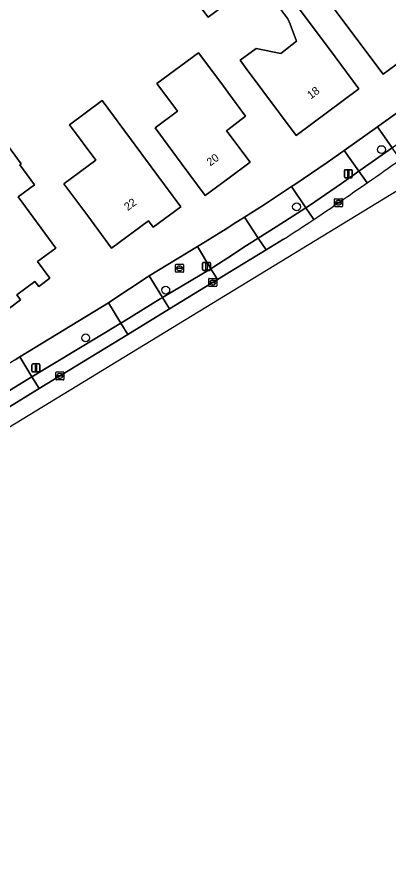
# Model space of a CAD drawing. Extents: x 156702 to 158052, y 387630 to 388992.
# Drawn here: x 157473.7 to 157520.1, y 387761.3 to 387868.3 of the extents above; entities that cross this region are included whole.
import ezdxf

# ---------------------------------------------------------------- set-up
doc = ezdxf.new("R2010")
doc.units = 0
for name, color, linetype in [('IMGEO_Boom', 7, 'Continuous'), ('IMGEO_Brandkraan', 7, 'Continuous'), ('IMGEO_Erf', 7, 'Continuous'), ('IMGEO_Kolk', 7, 'Continuous'), ('IMGEO_Lichtmast', 7, 'Continuous'), ('IMGEO_Pand', 7, 'Continuous'), ('IMGEO_Pand_nummerreeks', 7, 'Continuous'), ('IMGEO_Parkeervlak_open', 7, 'Continuous'), ('IMGEO_Rijbaan_lokaal_open', 7, 'Continuous'), ('IMGEO_Voetpad_open', 7, 'Continuous')]:
    doc.layers.add(name, color=color, linetype=linetype)

msp = doc.modelspace()

# ---------------------------------------------------------------- linework, layer by layer
at = {"layer": 'IMGEO_Boom'}
for centre in [(157519.17, 387851.76), (157508.58, 387844.62), (157492.26, 387834.21), (157482.27, 387828.25)]:
    msp.add_circle(centre, 0.489, dxfattribs=at)
at = {"layer": 'IMGEO_Brandkraan'}
for p, q in [((157493.48, 387836.52), (157493.48, 387837.37)), ((157493.56, 387837.44), (157494.41, 387837.44)), ((157493.74, 387836.94), (157493.74, 387836.95)), ((157494.18, 387836.9), (157493.78, 387836.9)), ((157493.79, 387836.99), (157494.18, 387836.99)), ((157493.97, 387837.22), (157494, 387837.22)), ((157493.99, 387836.66), (157493.97, 387836.66)), ((157494.23, 387836.95), (157494.23, 387836.94)), ((157494.48, 387837.37), (157494.48, 387836.52)), ((157494.41, 387836.44), (157493.56, 387836.44))]:
    msp.add_line(p, q, dxfattribs=at)
for points in [[(157493.48, 387836.52), (157493.48, 387837.37)], [(157493.56, 387837.44), (157494.41, 387837.44)], [(157494.48, 387837.37), (157494.48, 387836.52)], [(157494.41, 387836.44), (157493.56, 387836.44)]]:
    msp.add_lwpolyline(points, dxfattribs=at)
for centre, radius, start, end in [((157493.56, 387837.37), 0.0765, 91.552, 178.448), ((157493.56, 387837.37), 0.0765, 91.552, 178.448), ((157493.56, 387836.52), 0.0765, 181.552, 268.448), ((157493.56, 387836.52), 0.0765, 181.552, 268.448), ((157493.78, 387836.95), 0.0403, 85.8775, 175.7526), ((157493.78, 387836.94), 0.0366, 178.938, 274.7102), ((157494.19, 387836.95), 0.0386, 1.7309, 96.639), ((157494.18, 387836.94), 0.043, 264.8664, 352.4533), ((157494.41, 387837.37), 0.0765, 1.552, 88.448), ((157494.41, 387837.37), 0.0765, 1.552, 88.448), ((157494.41, 387836.52), 0.0765, 271.552, 358.448), ((157494.41, 387836.52), 0.0765, 271.552, 358.448)]:
    msp.add_arc(centre, radius, start, end, dxfattribs=at)
for centre, major_axis, ratio, start_param, end_param in [((157493.97, 387836.94), (-0.387, 0.002), 0.722429, 4.712389, 7.853982), ((157493.99, 387836.94), (-0.39, 0.002), 0.717154, 1.570796, 4.712389)]:
    msp.add_ellipse(centre, major_axis=major_axis, ratio=ratio, start_param=start_param, end_param=end_param, dxfattribs=at)
at = {"layer": 'IMGEO_Erf'}
for points in [[(157500, 387879.97), (157500.65, 387880.45), (157513.38, 387863.36), (157516.36, 387859.35), (157508.54, 387853.53), (157502.31, 387861.9), (157501.54, 387862.92), (157503.54, 387864.37), (157506.6, 387863.76), (157508.57, 387865.29), (157507.77, 387867.43), (157507.48, 387868.08), (157506.51, 387869.44), (157505.67, 387870.37), (157504.42, 387871.38), (157503.12, 387872.02), (157502.62, 387872.09), (157497.54, 387868.3), (157493.49, 387873.73), (157498.37, 387877.33), (157497.69, 387878.26)], [(157493.74, 387856.55), (157491.16, 387860.02), (157496.36, 387863.84), (157499.24, 387859.96), (157500, 387858.94), (157502.22, 387855.95), (157500, 387854.25), (157499.83, 387854.12), (157500, 387853.89), (157502.79, 387850.2), (157500, 387848.13), (157497.17, 387846.03), (157494.2, 387850.05), (157490.94, 387854.48)], [(157474.22, 387849.97), (157474.06, 387849.86), (157475.9, 387847.36), (157473.86, 387845.86), (157478.56, 387839.47), (157476.28, 387837.79), (157477.82, 387835.7), (157476.42, 387834.66), (157475.95, 387835.29), (157473.68, 387833.61), (157474.15, 387832.98), (157472.76, 387831.95), (157471.2, 387834.05), (157468.89, 387832.35), (157465.93, 387836.38), (157463, 387840.37), (157469.44, 387845.13), (157462.05, 387855.11), (157467.49, 387859.13)], [(157491.16, 387848.65), (157494.14, 387844.63), (157490.69, 387842.08), (157490.11, 387842.86), (157485.51, 387839.46), (157482.53, 387843.48), (157479.56, 387847.49), (157483.54, 387850.44), (157480.26, 387854.87), (157484.32, 387857.88)]]:
    msp.add_lwpolyline(points, close=True, dxfattribs=at)
for points in [[(157522.54, 387863.5), (157519.36, 387861.18), (157513.12, 387869.55)], [(157473.47, 387825.5), (157474.06, 387825.86), (157485.11, 387832.61), (157485.54, 387832.9), (157489.93, 387835.81), (157490.2, 387835.98), (157496.21, 387839.65), (157496.62, 387839.9), (157500, 387842), (157500.69, 387842.43), (157502.09, 387843.33), (157504.44, 387844.83), (157507.95, 387847.15), (157508.36, 387847.41), (157512.39, 387850.15), (157514.51, 387851.65), (157518.69, 387854.59), (157519.15, 387854.92), (157522.93, 387857.66)]]:
    msp.add_lwpolyline(points, dxfattribs=at)
at = {"layer": 'IMGEO_Kolk'}
for p, q in [((157513.31, 387844.71), (157513.31, 387845.56)), ((157513.39, 387845.63), (157514.24, 387845.63)), ((157513.57, 387845.13), (157513.57, 387845.14)), ((157513.61, 387845.18), (157514.01, 387845.18)), ((157514.01, 387845.09), (157513.61, 387845.09)), ((157513.8, 387845.41), (157513.82, 387845.41)), ((157514.05, 387845.14), (157514.05, 387845.13)), ((157514.31, 387845.56), (157514.31, 387844.71)), ((157514.24, 387844.63), (157513.39, 387844.63)), ((157513.82, 387844.85), (157513.8, 387844.85)), ((157497.62, 387834.74), (157497.62, 387835.59)), ((157497.69, 387835.67), (157498.54, 387835.67)), ((157498.11, 387835.44), (157498.13, 387835.44)), ((157498.62, 387835.59), (157498.62, 387834.74)), ((157498.54, 387834.66), (157497.69, 387834.66)), ((157497.88, 387835.16), (157497.88, 387835.17)), ((157497.92, 387835.21), (157498.32, 387835.21)), ((157498.31, 387835.12), (157497.92, 387835.12)), ((157498.13, 387834.89), (157498.1, 387834.89)), ((157498.36, 387835.17), (157498.36, 387835.16)), ((157478.55, 387823.08), (157478.55, 387823.93)), ((157478.63, 387824), (157479.48, 387824)), ((157479.04, 387823.78), (157479.06, 387823.78)), ((157479.55, 387823.93), (157479.55, 387823.08)), ((157479.48, 387823), (157478.63, 387823)), ((157478.81, 387823.5), (157478.81, 387823.51)), ((157478.85, 387823.55), (157479.25, 387823.55)), ((157479.25, 387823.46), (157478.85, 387823.46)), ((157479.06, 387823.22), (157479.04, 387823.22)), ((157479.29, 387823.51), (157479.29, 387823.5))]:
    msp.add_line(p, q, dxfattribs=at)
for points in [[(157513.31, 387844.71), (157513.31, 387845.56)], [(157513.39, 387845.63), (157514.24, 387845.63)], [(157514.31, 387845.56), (157514.31, 387844.71)], [(157514.24, 387844.63), (157513.39, 387844.63)], [(157497.62, 387834.74), (157497.62, 387835.59)], [(157497.69, 387835.67), (157498.54, 387835.67)], [(157498.62, 387835.59), (157498.62, 387834.74)], [(157498.54, 387834.66), (157497.69, 387834.66)], [(157478.55, 387823.08), (157478.55, 387823.93)], [(157478.63, 387824), (157479.48, 387824)], [(157479.55, 387823.93), (157479.55, 387823.08)], [(157479.48, 387823), (157478.63, 387823)]]:
    msp.add_lwpolyline(points, dxfattribs=at)
for centre, radius, start, end in [((157513.39, 387845.56), 0.0765, 91.552, 178.448), ((157513.39, 387845.56), 0.0765, 91.552, 178.448), ((157513.61, 387845.14), 0.0403, 85.8775, 175.7526), ((157513.61, 387845.13), 0.0366, 178.938, 274.7102), ((157514.02, 387845.14), 0.0386, 1.7309, 96.639), ((157514.01, 387845.13), 0.043, 264.8664, 352.4533), ((157514.24, 387845.56), 0.0765, 1.552, 88.448), ((157514.24, 387845.56), 0.0765, 1.552, 88.448), ((157513.39, 387844.71), 0.0765, 181.552, 268.448), ((157513.39, 387844.71), 0.0765, 181.552, 268.448), ((157514.24, 387844.71), 0.0765, 271.552, 358.448), ((157514.24, 387844.71), 0.0765, 271.552, 358.448), ((157497.69, 387835.59), 0.0765, 91.552, 178.448), ((157497.69, 387835.59), 0.0765, 91.552, 178.448), ((157498.54, 387835.59), 0.0765, 1.552, 88.448), ((157498.54, 387835.59), 0.0765, 1.552, 88.448), ((157497.69, 387834.74), 0.0765, 181.552, 268.448), ((157497.69, 387834.74), 0.0765, 181.552, 268.448), ((157497.92, 387835.17), 0.0403, 85.8775, 175.7526), ((157497.91, 387835.16), 0.0366, 178.938, 274.7102), ((157498.32, 387835.16), 0.043, 264.8664, 352.4533), ((157498.32, 387835.17), 0.0386, 1.7309, 96.639), ((157498.54, 387834.74), 0.0765, 271.552, 358.448), ((157498.54, 387834.74), 0.0765, 271.552, 358.448), ((157478.63, 387823.93), 0.0765, 91.552, 178.448), ((157478.63, 387823.93), 0.0765, 91.552, 178.448), ((157479.48, 387823.93), 0.0765, 1.552, 88.448), ((157479.48, 387823.93), 0.0765, 1.552, 88.448), ((157478.63, 387823.08), 0.0765, 181.552, 268.448), ((157478.63, 387823.08), 0.0765, 181.552, 268.448), ((157478.85, 387823.51), 0.0403, 85.8775, 175.7526), ((157478.85, 387823.5), 0.0366, 178.938, 274.7102), ((157479.26, 387823.51), 0.0386, 1.7309, 96.639), ((157479.25, 387823.5), 0.043, 264.8664, 352.4533), ((157479.48, 387823.08), 0.0765, 271.552, 358.448), ((157479.48, 387823.08), 0.0765, 271.552, 358.448)]:
    msp.add_arc(centre, radius, start, end, dxfattribs=at)
for centre, major_axis, ratio, start_param, end_param in [((157513.8, 387845.13), (-0.387, 0.002), 0.722429, 4.712389, 7.853982), ((157513.82, 387845.13), (-0.39, 0.002), 0.717154, 1.570796, 4.712389), ((157498.1, 387835.16), (-0.387, 0.002), 0.722429, 4.712389, 7.853982), ((157498.13, 387835.16), (-0.39, 0.002), 0.717154, 1.570796, 4.712389), ((157479.04, 387823.5), (-0.387, 0.002), 0.722429, 4.712389, 7.853982), ((157479.06, 387823.5), (-0.39, 0.002), 0.717154, 1.570796, 4.712389)]:
    msp.add_ellipse(centre, major_axis=major_axis, ratio=ratio, start_param=start_param, end_param=end_param, dxfattribs=at)
at = {"layer": 'IMGEO_Lichtmast'}
for p, q in [((157514.54, 387848.35), (157514.54, 387849.15)), ((157514.54, 387849.15), (157514.54, 387848.35)), ((157514.64, 387849.25), (157515.43, 387849.25)), ((157515.43, 387849.25), (157514.64, 387849.25)), ((157515.43, 387848.25), (157514.64, 387848.25)), ((157514.64, 387848.25), (157515.43, 387848.25)), ((157515.53, 387849.15), (157515.53, 387848.35)), ((157515.53, 387848.35), (157515.53, 387849.15)), ((157496.86, 387836.78), (157496.86, 387837.58)), ((157496.86, 387837.58), (157496.86, 387836.78)), ((157496.96, 387837.68), (157497.75, 387837.68)), ((157497.75, 387837.68), (157496.96, 387837.68)), ((157497.85, 387837.58), (157497.85, 387836.78)), ((157497.85, 387836.78), (157497.85, 387837.58)), ((157497.75, 387836.68), (157496.96, 387836.68)), ((157496.96, 387836.68), (157497.75, 387836.68)), ((157475.58, 387824.09), (157475.58, 387824.89)), ((157475.58, 387824.89), (157475.58, 387824.09)), ((157475.68, 387824.99), (157476.47, 387824.99)), ((157476.47, 387824.99), (157475.68, 387824.99)), ((157476.57, 387824.89), (157476.57, 387824.09)), ((157476.57, 387824.09), (157476.57, 387824.89)), ((157476.47, 387823.99), (157475.68, 387823.99)), ((157475.68, 387823.99), (157476.47, 387823.99))]:
    msp.add_line(p, q, dxfattribs=at)
for points in [[(157514.96, 387849.13), (157515.11, 387849.13), (157515.11, 387848.38), (157514.96, 387848.38), (157514.96, 387849.13)], [(157497.28, 387837.55), (157497.43, 387837.55), (157497.43, 387836.8), (157497.28, 387836.8), (157497.28, 387837.55)], [(157476, 387824.86), (157476.15, 387824.86), (157476.15, 387824.11), (157476, 387824.11), (157476, 387824.86)]]:
    msp.add_lwpolyline(points, dxfattribs=at)
for centre, start, end in [((157514.64, 387849.15), 90, 180), ((157514.64, 387849.15), 90, 180), ((157514.64, 387848.35), 180, 270), ((157514.64, 387848.35), 180, 270), ((157515.43, 387849.15), 0, 90), ((157515.43, 387849.15), 360, 90), ((157515.43, 387848.35), 270, 0), ((157515.43, 387848.35), 270, 0), ((157496.96, 387837.58), 90, 180), ((157496.96, 387837.58), 90, 180), ((157497.75, 387837.58), 0, 90), ((157497.75, 387837.58), 360, 90), ((157496.96, 387836.78), 180, 270), ((157496.96, 387836.78), 180, 270), ((157497.75, 387836.78), 270, 0), ((157497.75, 387836.78), 270, 0), ((157475.68, 387824.89), 90, 180), ((157475.68, 387824.89), 90, 180), ((157476.47, 387824.89), 0, 90), ((157476.47, 387824.89), 360, 90), ((157475.68, 387824.09), 180, 270), ((157475.68, 387824.09), 180, 270), ((157476.47, 387824.09), 270, 0), ((157476.47, 387824.09), 270, 0)]:
    msp.add_arc(centre, 0.1, start, end, dxfattribs=at)
at = {"layer": 'IMGEO_Pand'}
for points in [[(157512.01, 387887.37), (157511.45, 387888.12), (157508.5, 387885.93), (157509.18, 387885), (157504.32, 387881.39), (157508.36, 387875.96), (157513.44, 387879.74), (157514.15, 387879.92), (157514.65, 387879.92), (157515.33, 387879.66), (157515.88, 387879.23), (157516.4, 387878.64), (157517.21, 387877.33), (157517.92, 387875.55), (157518.43, 387873.51), (157518.2, 387873.34), (157513.12, 387869.55), (157519.36, 387861.18), (157522.54, 387863.5), (157527.15, 387866.93), (157525.58, 387869.06)], [(157507.77, 387867.43), (157508.57, 387865.29), (157506.6, 387863.76), (157503.54, 387864.37), (157501.54, 387862.92), (157502.31, 387861.9), (157508.54, 387853.53), (157516.36, 387859.35), (157513.38, 387863.36), (157500.65, 387880.45), (157500, 387879.97), (157497.69, 387878.26), (157498.37, 387877.33), (157493.49, 387873.73), (157497.54, 387868.3), (157502.62, 387872.09), (157503.12, 387872.02), (157504.42, 387871.38), (157505.67, 387870.37), (157506.51, 387869.44), (157507.48, 387868.08)], [(157494.2, 387850.05), (157497.17, 387846.03), (157500, 387848.13), (157502.79, 387850.2), (157500, 387853.89), (157499.83, 387854.12), (157500, 387854.25), (157502.22, 387855.95), (157500, 387858.94), (157499.24, 387859.96), (157496.36, 387863.84), (157491.16, 387860.02), (157493.74, 387856.55), (157490.94, 387854.48)], [(157474.15, 387832.98), (157473.68, 387833.61), (157475.95, 387835.29), (157476.42, 387834.66), (157477.82, 387835.7), (157476.28, 387837.79), (157478.56, 387839.47), (157473.86, 387845.86), (157475.9, 387847.36), (157474.06, 387849.86), (157474.22, 387849.97), (157467.49, 387859.13), (157462.05, 387855.11), (157469.44, 387845.13), (157463, 387840.37), (157465.93, 387836.38), (157468.89, 387832.35), (157471.2, 387834.05), (157472.76, 387831.95)], [(157491.16, 387848.65), (157484.32, 387857.88), (157480.26, 387854.87), (157483.54, 387850.44), (157479.56, 387847.49), (157482.53, 387843.48), (157485.51, 387839.46), (157490.11, 387842.86), (157490.69, 387842.08), (157494.14, 387844.63)]]:
    msp.add_lwpolyline(points, close=True, dxfattribs=at)
at = {"layer": 'IMGEO_Parkeervlak_open'}
for points in [[(157521.55, 387850.54), (157520.52, 387852), (157516.36, 387849.07), (157517.4, 387847.61)], [(157510.72, 387843.02), (157509.73, 387844.5), (157506.02, 387842.12), (157503.8, 387840.71), (157504.77, 387839.23), (157506.97, 387840.58)]]:
    msp.add_lwpolyline(points, dxfattribs=at)
for points in [[(157498.72, 387835.53), (157497.89, 387836.89), (157491.85, 387833.28), (157492.72, 387831.86)], [(157487.52, 387828.68), (157486.65, 387830.1), (157475.57, 387823.39), (157476.47, 387821.92)]]:
    msp.add_lwpolyline(points, close=True, dxfattribs=at)
for centre, radius, start, end in [((157355.09, 388081.03), 284.31, 304.8122, 305.8355), ((157397.84, 388012.04), 203.24, 302.4733, 303.7363)]:
    msp.add_arc(centre, radius, start, end, dxfattribs=at)
at = {"layer": 'IMGEO_Rijbaan_lokaal_open'}
for points in [[(157393.08, 387676.28), (157404.02, 387683.17), (157415.85, 387729.44), (157428.09, 387777.36), (157443.62, 387799.36), (157522.84, 387847.69), (157543.93, 387864.19), (157542.28, 387866.17), (157541.22, 387865.32), (157540.15, 387864.48)], [(157506.97, 387840.58), (157504.77, 387839.23), (157500, 387836.31), (157498.72, 387835.53), (157492.72, 387831.86), (157487.52, 387828.68), (157476.47, 387821.92), (157471.31, 387818.77), (157464.47, 387814.58), (157463, 387813.68), (157456.38, 387809.71), (157455.81, 387809.37)]]:
    msp.add_lwpolyline(points, dxfattribs=at)
for centre, radius, start, end in [((157355.09, 388081.03), 284.31, 304.8122, 305.8355), ((157368.93, 388061.32), 260.22, 304.1308, 304.7896), ((157398.93, 388010.36), 201.24, 303.7454, 305.2012), ((157397.84, 388012.04), 203.24, 302.4733, 303.7363)]:
    msp.add_arc(centre, radius, start, end, dxfattribs=at)
at = {"layer": 'IMGEO_Voetpad_open'}
for points in [[(157524.77, 387855.09), (157526.85, 387856.63), (157524.98, 387859.2), (157522.93, 387857.66), (157519.15, 387854.92), (157518.69, 387854.59), (157520.52, 387852), (157520.99, 387852.34)], [(157520.52, 387852), (157518.69, 387854.59), (157514.51, 387851.65), (157516.36, 387849.07)], [(157514.19, 387847.53), (157516.36, 387849.07), (157514.51, 387851.65), (157512.39, 387850.15), (157508.36, 387847.41), (157507.95, 387847.15), (157509.73, 387844.5), (157510.18, 387844.79)], [(157509.73, 387844.5), (157507.95, 387847.15), (157504.44, 387844.83), (157502.09, 387843.33), (157503.8, 387840.71), (157506.02, 387842.12)], [(157502.34, 387839.77), (157503.8, 387840.71), (157502.09, 387843.33), (157500.69, 387842.43), (157500, 387842), (157496.62, 387839.9), (157496.21, 387839.65), (157497.89, 387836.89), (157498.27, 387837.12), (157500, 387838.25)], [(157504.77, 387839.23), (157503.8, 387840.71), (157502.34, 387839.77), (157500, 387838.25), (157498.27, 387837.12), (157497.89, 387836.89), (157498.72, 387835.53), (157500, 387836.31)], [(157497.89, 387836.89), (157496.21, 387839.65), (157490.2, 387835.98), (157491.85, 387833.28)], [(157491.85, 387833.28), (157490.2, 387835.98), (157489.93, 387835.81), (157485.54, 387832.9), (157485.11, 387832.61), (157486.65, 387830.1), (157487.07, 387830.35), (157491.58, 387833.11)], [(157492.72, 387831.86), (157491.85, 387833.28), (157491.58, 387833.11), (157487.07, 387830.35), (157486.65, 387830.1), (157487.52, 387828.68)], [(157486.65, 387830.1), (157485.11, 387832.61), (157474.06, 387825.86), (157475.57, 387823.39)], [(157474.06, 387825.86), (157473.47, 387825.5), (157469.28, 387822.93), (157468.9, 387822.71), (157470.41, 387820.25), (157470.77, 387820.47), (157474.93, 387823), (157475.57, 387823.39)], [(157476.47, 387821.92), (157475.57, 387823.39), (157474.93, 387823), (157470.77, 387820.47), (157470.41, 387820.25), (157471.31, 387818.77)]]:
    msp.add_lwpolyline(points, close=True, dxfattribs=at)
msp.add_lwpolyline([(157517.4, 387847.61), (157516.36, 387849.07), (157514.19, 387847.53), (157510.18, 387844.79), (157509.73, 387844.5), (157510.72, 387843.02)], dxfattribs=at)
for centre, radius, start, end in [((157368.93, 388061.32), 260.22, 304.1308, 304.7896), ((157398.93, 388010.36), 201.24, 303.7454, 305.2012)]:
    msp.add_arc(centre, radius, start, end, dxfattribs=at)

# ---------------------------------------------------------------- texts
at = {"layer": 'IMGEO_Pand_nummerreeks'}
for s, rotation, p in [('18', 36.6712, (157510.36, 387858.02)), ('20', 36.6422, (157497.82, 387849.65)), ('22', 36.5018, (157487.52, 387844.08))]:
    msp.add_text(s, height=1, rotation=rotation, dxfattribs=at).set_placement(p)

doc.saveas('drawing.dxf')
